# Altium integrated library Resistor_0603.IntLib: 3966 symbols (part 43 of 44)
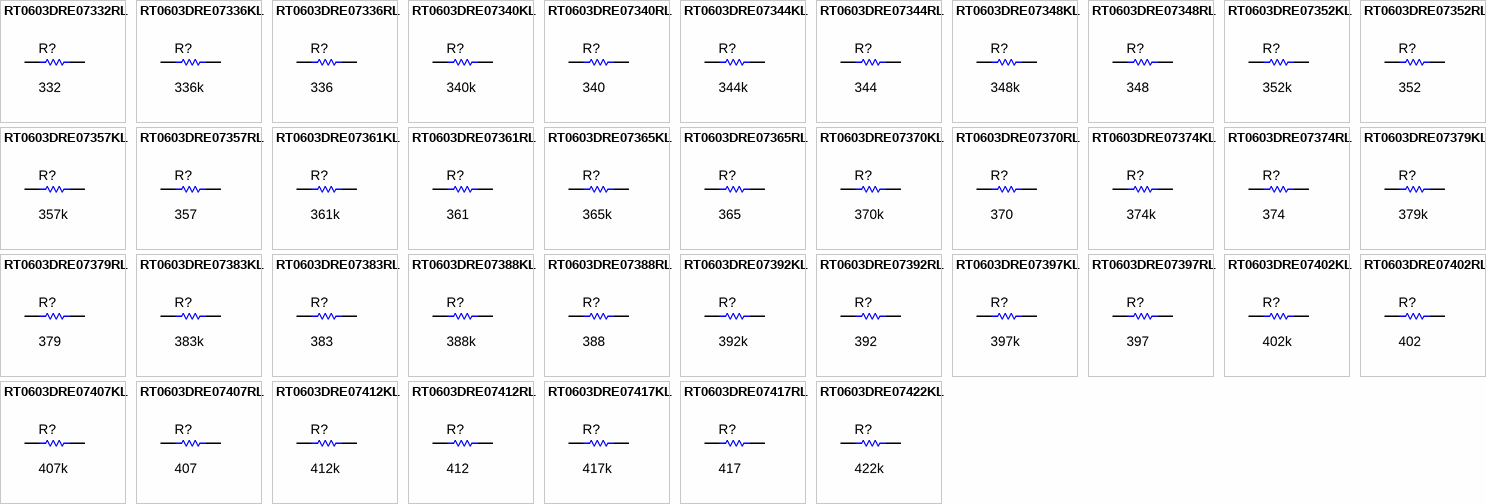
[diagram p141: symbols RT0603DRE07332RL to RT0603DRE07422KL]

## RT0603DRE07422KL
designator R?  ValueDisplayed: 422k  (hidden comment: RT0603DRE07422KL)
RES, 422 k, 0.5%, 0.1 W, 0603; Manufacturer: Yageo America; CompType: Resistor; Value: 422k; Res_ohm: 422000; Tolerance_%: 0.5; Power_W: 0.1; Value2: 0.1W; VDC_V: 75; TempCo: 50 ppm/C; SizeArea_mm2: 1.28; SizeX_mm: 1.6; SizeY_mm: 0.8; SizeZ_mm: 1; EIA_Code: E192; U/M: EA; AEC Category: Q200
signal-integrity model Resistor
simulation model Resistor
footprint 0603
footprint 0603M
footprint 0603L
footprint 0603_HV
footprint 0603S
pins: 1, 2

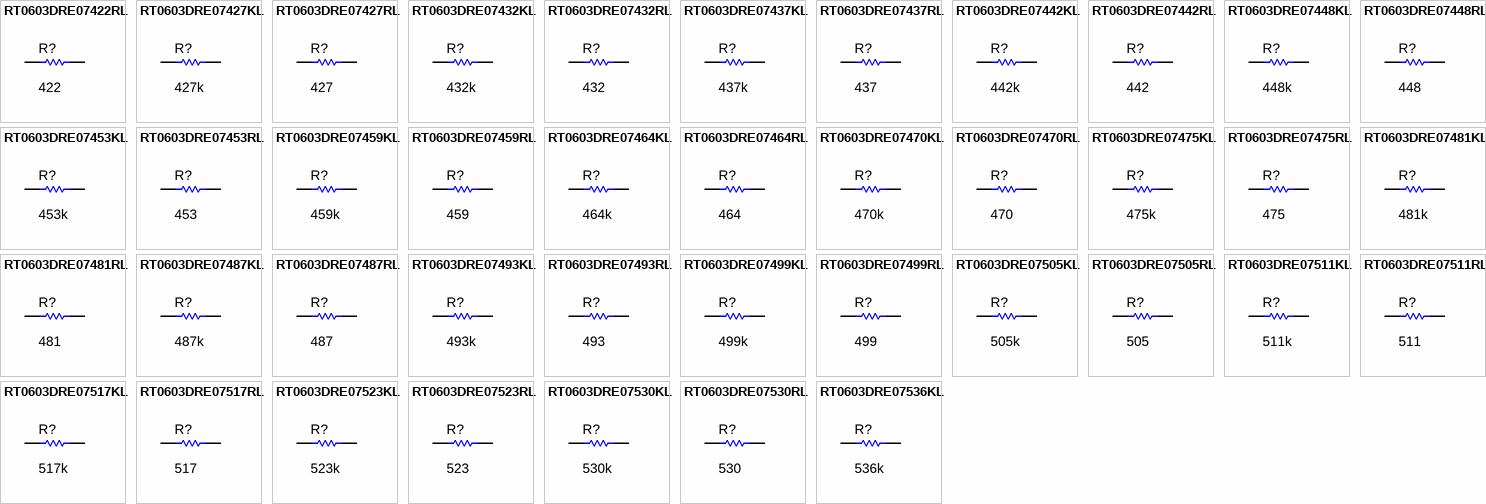
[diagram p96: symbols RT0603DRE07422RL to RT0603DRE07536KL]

## RT0603DRE07422RL
designator R?  ValueDisplayed: 422  (hidden comment: RT0603DRE07422RL)
RES, 422, 0.5%, 0.1 W, 0603; Manufacturer: Yageo America; CompType: Resistor; Value: 422; Value_Code: 422R; Tolerance_%: 0.5; Power_W: 0.1; Value2: 0.1W; VDC_V: 75; TempCo: 50 ppm/C; SizeArea_mm2: 1.28; SizeX_mm: 1.6; SizeY_mm: 0.8; SizeZ_mm: 1; EIA_Code: E192; U/M: EA; AEC Category: Q200
signal-integrity model Resistor
simulation model Resistor
footprint 0603
footprint 0603M
footprint 0603L
footprint 0603_HV
footprint 0603S
pins: 1, 2

## RT0603DRE07427KL
designator R?  ValueDisplayed: 427k  (hidden comment: RT0603DRE07427KL)
RES, 427 k, 0.5%, 0.1 W, 0603; Manufacturer: Yageo America; CompType: Resistor; Value: 427k; Res_ohm: 427000; Tolerance_%: 0.5; Power_W: 0.1; Value2: 0.1W; VDC_V: 75; TempCo: 50 ppm/C; SizeArea_mm2: 1.28; SizeX_mm: 1.6; SizeY_mm: 0.8; SizeZ_mm: 1; EIA_Code: E192; U/M: EA; AEC Category: Q200
signal-integrity model Resistor
simulation model Resistor
footprint 0603
footprint 0603M
footprint 0603L
footprint 0603_HV
footprint 0603S
pins: 1, 2

## RT0603DRE07427RL
designator R?  ValueDisplayed: 427  (hidden comment: RT0603DRE07427RL)
RES, 427, 0.5%, 0.1 W, 0603; Manufacturer: Yageo America; CompType: Resistor; Value: 427; Value_Code: 427R; Tolerance_%: 0.5; Power_W: 0.1; Value2: 0.1W; VDC_V: 75; TempCo: 50 ppm/C; SizeArea_mm2: 1.28; SizeX_mm: 1.6; SizeY_mm: 0.8; SizeZ_mm: 1; EIA_Code: E192; U/M: EA; AEC Category: Q200
signal-integrity model Resistor
simulation model Resistor
footprint 0603
footprint 0603M
footprint 0603L
footprint 0603_HV
footprint 0603S
pins: 1, 2

## RT0603DRE07432KL
designator R?  ValueDisplayed: 432k  (hidden comment: RT0603DRE07432KL)
RES, 432 k, 0.5%, 0.1 W, 0603; Manufacturer: Yageo America; CompType: Resistor; Value: 432k; Res_ohm: 432000; Tolerance_%: 0.5; Power_W: 0.1; Value2: 0.1W; VDC_V: 75; TempCo: 50 ppm/C; SizeArea_mm2: 1.28; SizeX_mm: 1.6; SizeY_mm: 0.8; SizeZ_mm: 1; EIA_Code: E192; U/M: EA; AEC Category: Q200
signal-integrity model Resistor
simulation model Resistor
footprint 0603
footprint 0603M
footprint 0603L
footprint 0603_HV
footprint 0603S
pins: 1, 2

## RT0603DRE07432RL
designator R?  ValueDisplayed: 432  (hidden comment: RT0603DRE07432RL)
RES, 432, 0.5%, 0.1 W, 0603; Manufacturer: Yageo America; CompType: Resistor; Value: 432; Value_Code: 432R; Tolerance_%: 0.5; Power_W: 0.1; Value2: 0.1W; VDC_V: 75; TempCo: 50 ppm/C; SizeArea_mm2: 1.28; SizeX_mm: 1.6; SizeY_mm: 0.8; SizeZ_mm: 1; EIA_Code: E192; U/M: EA; AEC Category: Q200
signal-integrity model Resistor
simulation model Resistor
footprint 0603
footprint 0603M
footprint 0603L
footprint 0603_HV
footprint 0603S
pins: 1, 2

## RT0603DRE07437KL
designator R?  ValueDisplayed: 437k  (hidden comment: RT0603DRE07437KL)
RES, 437 k, 0.5%, 0.1 W, 0603; Manufacturer: Yageo America; CompType: Resistor; Value: 437k; Res_ohm: 437000; Tolerance_%: 0.5; Power_W: 0.1; Value2: 0.1W; VDC_V: 75; TempCo: 50 ppm/C; SizeArea_mm2: 1.28; SizeX_mm: 1.6; SizeY_mm: 0.8; SizeZ_mm: 1; EIA_Code: E192; U/M: EA; AEC Category: Q200
signal-integrity model Resistor
simulation model Resistor
footprint 0603
footprint 0603M
footprint 0603L
footprint 0603_HV
footprint 0603S
pins: 1, 2

## RT0603DRE07437RL
designator R?  ValueDisplayed: 437  (hidden comment: RT0603DRE07437RL)
RES, 437, 0.5%, 0.1 W, 0603; Manufacturer: Yageo America; CompType: Resistor; Value: 437; Value_Code: 437R; Tolerance_%: 0.5; Power_W: 0.1; Value2: 0.1W; VDC_V: 75; TempCo: 50 ppm/C; SizeArea_mm2: 1.28; SizeX_mm: 1.6; SizeY_mm: 0.8; SizeZ_mm: 1; EIA_Code: E192; U/M: EA; AEC Category: Q200
signal-integrity model Resistor
simulation model Resistor
footprint 0603
footprint 0603M
footprint 0603L
footprint 0603_HV
footprint 0603S
pins: 1, 2

## RT0603DRE07442KL
designator R?  ValueDisplayed: 442k  (hidden comment: RT0603DRE07442KL)
RES, 442 k, 0.5%, 0.1 W, 0603; Manufacturer: Yageo America; CompType: Resistor; Value: 442k; Res_ohm: 442000; Tolerance_%: 0.5; Power_W: 0.1; Value2: 0.1W; VDC_V: 75; TempCo: 50 ppm/C; SizeArea_mm2: 1.28; SizeX_mm: 1.6; SizeY_mm: 0.8; SizeZ_mm: 1; EIA_Code: E192; U/M: EA; AEC Category: Q200
signal-integrity model Resistor
simulation model Resistor
footprint 0603
footprint 0603M
footprint 0603L
footprint 0603_HV
footprint 0603S
pins: 1, 2

## RT0603DRE07442RL
designator R?  ValueDisplayed: 442  (hidden comment: RT0603DRE07442RL)
RES, 442, 0.5%, 0.1 W, 0603; Manufacturer: Yageo America; CompType: Resistor; Value: 442; Value_Code: 442R; Tolerance_%: 0.5; Power_W: 0.1; Value2: 0.1W; VDC_V: 75; TempCo: 50 ppm/C; SizeArea_mm2: 1.28; SizeX_mm: 1.6; SizeY_mm: 0.8; SizeZ_mm: 1; EIA_Code: E192; U/M: EA; AEC Category: Q200
signal-integrity model Resistor
simulation model Resistor
footprint 0603
footprint 0603M
footprint 0603L
footprint 0603_HV
footprint 0603S
pins: 1, 2

## RT0603DRE07448KL
designator R?  ValueDisplayed: 448k  (hidden comment: RT0603DRE07448KL)
RES, 448 k, 0.5%, 0.1 W, 0603; Manufacturer: Yageo America; CompType: Resistor; Value: 448k; Res_ohm: 448000; Tolerance_%: 0.5; Power_W: 0.1; Value2: 0.1W; VDC_V: 75; TempCo: 50 ppm/C; SizeArea_mm2: 1.28; SizeX_mm: 1.6; SizeY_mm: 0.8; SizeZ_mm: 1; EIA_Code: E192; U/M: EA; AEC Category: Q200
signal-integrity model Resistor
simulation model Resistor
footprint 0603
footprint 0603M
footprint 0603L
footprint 0603_HV
footprint 0603S
pins: 1, 2

## RT0603DRE07448RL
designator R?  ValueDisplayed: 448  (hidden comment: RT0603DRE07448RL)
RES, 448, 0.5%, 0.1 W, 0603; Manufacturer: Yageo America; CompType: Resistor; Value: 448; Value_Code: 448R; Tolerance_%: 0.5; Power_W: 0.1; Value2: 0.1W; VDC_V: 75; TempCo: 50 ppm/C; SizeArea_mm2: 1.28; SizeX_mm: 1.6; SizeY_mm: 0.8; SizeZ_mm: 1; EIA_Code: E192; U/M: EA; AEC Category: Q200
signal-integrity model Resistor
simulation model Resistor
footprint 0603
footprint 0603M
footprint 0603L
footprint 0603_HV
footprint 0603S
pins: 1, 2

## RT0603DRE07453KL
designator R?  ValueDisplayed: 453k  (hidden comment: RT0603DRE07453KL)
RES, 453 k, 0.5%, 0.1 W, 0603; Manufacturer: Yageo America; CompType: Resistor; Value: 453k; Res_ohm: 453000; Tolerance_%: 0.5; Power_W: 0.1; Value2: 0.1W; VDC_V: 75; TempCo: 50 ppm/C; SizeArea_mm2: 1.28; SizeX_mm: 1.6; SizeY_mm: 0.8; SizeZ_mm: 1; EIA_Code: E192; U/M: EA; AEC Category: Q200
signal-integrity model Resistor
simulation model Resistor
footprint 0603
footprint 0603M
footprint 0603L
footprint 0603_HV
footprint 0603S
pins: 1, 2

## RT0603DRE07453RL
designator R?  ValueDisplayed: 453  (hidden comment: RT0603DRE07453RL)
RES, 453, 0.5%, 0.1 W, 0603; Manufacturer: Yageo America; CompType: Resistor; Value: 453; Value_Code: 453R; Tolerance_%: 0.5; Power_W: 0.1; Value2: 0.1W; VDC_V: 75; TempCo: 50 ppm/C; SizeArea_mm2: 1.28; SizeX_mm: 1.6; SizeY_mm: 0.8; SizeZ_mm: 1; EIA_Code: E192; U/M: EA; AEC Category: Q200
signal-integrity model Resistor
simulation model Resistor
footprint 0603
footprint 0603M
footprint 0603L
footprint 0603_HV
footprint 0603S
pins: 1, 2

## RT0603DRE07459KL
designator R?  ValueDisplayed: 459k  (hidden comment: RT0603DRE07459KL)
RES, 459 k, 0.5%, 0.1 W, 0603; Manufacturer: Yageo America; CompType: Resistor; Value: 459k; Res_ohm: 459000; Tolerance_%: 0.5; Power_W: 0.1; Value2: 0.1W; VDC_V: 75; TempCo: 50 ppm/C; SizeArea_mm2: 1.28; SizeX_mm: 1.6; SizeY_mm: 0.8; SizeZ_mm: 1; EIA_Code: E192; U/M: EA; AEC Category: Q200
signal-integrity model Resistor
simulation model Resistor
footprint 0603
footprint 0603M
footprint 0603L
footprint 0603_HV
footprint 0603S
pins: 1, 2

## RT0603DRE07459RL
designator R?  ValueDisplayed: 459  (hidden comment: RT0603DRE07459RL)
RES, 459, 0.5%, 0.1 W, 0603; Manufacturer: Yageo America; CompType: Resistor; Value: 459; Value_Code: 459R; Tolerance_%: 0.5; Power_W: 0.1; Value2: 0.1W; VDC_V: 75; TempCo: 50 ppm/C; SizeArea_mm2: 1.28; SizeX_mm: 1.6; SizeY_mm: 0.8; SizeZ_mm: 1; EIA_Code: E192; U/M: EA; AEC Category: Q200
signal-integrity model Resistor
simulation model Resistor
footprint 0603
footprint 0603M
footprint 0603L
footprint 0603_HV
footprint 0603S
pins: 1, 2

## RT0603DRE07464KL
designator R?  ValueDisplayed: 464k  (hidden comment: RT0603DRE07464KL)
RES, 464 k, 0.5%, 0.1 W, 0603; Manufacturer: Yageo America; CompType: Resistor; Value: 464k; Res_ohm: 464000; Tolerance_%: 0.5; Power_W: 0.1; Value2: 0.1W; VDC_V: 75; TempCo: 50 ppm/C; SizeArea_mm2: 1.28; SizeX_mm: 1.6; SizeY_mm: 0.8; SizeZ_mm: 1; EIA_Code: E192; U/M: EA; AEC Category: Q200
signal-integrity model Resistor
simulation model Resistor
footprint 0603
footprint 0603M
footprint 0603L
footprint 0603_HV
footprint 0603S
pins: 1, 2

## RT0603DRE07464RL
designator R?  ValueDisplayed: 464  (hidden comment: RT0603DRE07464RL)
RES, 464, 0.5%, 0.1 W, 0603; Manufacturer: Yageo America; CompType: Resistor; Value: 464; Value_Code: 464R; Tolerance_%: 0.5; Power_W: 0.1; Value2: 0.1W; VDC_V: 75; TempCo: 50 ppm/C; SizeArea_mm2: 1.28; SizeX_mm: 1.6; SizeY_mm: 0.8; SizeZ_mm: 1; EIA_Code: E192; U/M: EA; AEC Category: Q200
signal-integrity model Resistor
simulation model Resistor
footprint 0603
footprint 0603M
footprint 0603L
footprint 0603_HV
footprint 0603S
pins: 1, 2

## RT0603DRE07470KL
designator R?  ValueDisplayed: 470k  (hidden comment: RT0603DRE07470KL)
RES, 470 k, 0.5%, 0.1 W, 0603; Manufacturer: Yageo America; CompType: Resistor; Value: 470k; Res_ohm: 470000; Tolerance_%: 0.5; Power_W: 0.1; Value2: 0.1W; VDC_V: 75; TempCo: 50 ppm/C; SizeArea_mm2: 1.28; SizeX_mm: 1.6; SizeY_mm: 0.8; SizeZ_mm: 1; EIA_Code: E192; U/M: EA; AEC Category: Q200
signal-integrity model Resistor
simulation model Resistor
footprint 0603
footprint 0603M
footprint 0603L
footprint 0603_HV
footprint 0603S
pins: 1, 2

## RT0603DRE07470RL
designator R?  ValueDisplayed: 470  (hidden comment: RT0603DRE07470RL)
RES, 470, 0.5%, 0.1 W, 0603; Manufacturer: Yageo America; CompType: Resistor; Value: 470; Value_Code: 470R; Tolerance_%: 0.5; Power_W: 0.1; Value2: 0.1W; VDC_V: 75; TempCo: 50 ppm/C; SizeArea_mm2: 1.28; SizeX_mm: 1.6; SizeY_mm: 0.8; SizeZ_mm: 1; EIA_Code: E192; U/M: EA; AEC Category: Q200
signal-integrity model Resistor
simulation model Resistor
footprint 0603
footprint 0603M
footprint 0603L
footprint 0603_HV
footprint 0603S
pins: 1, 2

## RT0603DRE07475KL
designator R?  ValueDisplayed: 475k  (hidden comment: RT0603DRE07475KL)
RES, 475 k, 0.5%, 0.1 W, 0603; Manufacturer: Yageo America; CompType: Resistor; Value: 475k; Res_ohm: 475000; Tolerance_%: 0.5; Power_W: 0.1; Value2: 0.1W; VDC_V: 75; TempCo: 50 ppm/C; SizeArea_mm2: 1.28; SizeX_mm: 1.6; SizeY_mm: 0.8; SizeZ_mm: 1; EIA_Code: E192; U/M: EA; AEC Category: Q200
signal-integrity model Resistor
simulation model Resistor
footprint 0603
footprint 0603M
footprint 0603L
footprint 0603_HV
footprint 0603S
pins: 1, 2

## RT0603DRE07475RL
designator R?  ValueDisplayed: 475  (hidden comment: RT0603DRE07475RL)
RES, 475, 0.5%, 0.1 W, 0603; Manufacturer: Yageo America; CompType: Resistor; Value: 475; Value_Code: 475R; Tolerance_%: 0.5; Power_W: 0.1; Value2: 0.1W; VDC_V: 75; TempCo: 50 ppm/C; SizeArea_mm2: 1.28; SizeX_mm: 1.6; SizeY_mm: 0.8; SizeZ_mm: 1; EIA_Code: E192; U/M: EA; AEC Category: Q200
signal-integrity model Resistor
simulation model Resistor
footprint 0603
footprint 0603M
footprint 0603L
footprint 0603_HV
footprint 0603S
pins: 1, 2

## RT0603DRE07481KL
designator R?  ValueDisplayed: 481k  (hidden comment: RT0603DRE07481KL)
RES, 481 k, 0.5%, 0.1 W, 0603; Manufacturer: Yageo America; CompType: Resistor; Value: 481k; Res_ohm: 481000; Tolerance_%: 0.5; Power_W: 0.1; Value2: 0.1W; VDC_V: 75; TempCo: 50 ppm/C; SizeArea_mm2: 1.28; SizeX_mm: 1.6; SizeY_mm: 0.8; SizeZ_mm: 1; EIA_Code: E192; U/M: EA; AEC Category: Q200
signal-integrity model Resistor
simulation model Resistor
footprint 0603
footprint 0603M
footprint 0603L
footprint 0603_HV
footprint 0603S
pins: 1, 2

## RT0603DRE07481RL
designator R?  ValueDisplayed: 481  (hidden comment: RT0603DRE07481RL)
RES, 481, 0.5%, 0.1 W, 0603; Manufacturer: Yageo America; CompType: Resistor; Value: 481; Value_Code: 481R; Tolerance_%: 0.5; Power_W: 0.1; Value2: 0.1W; VDC_V: 75; TempCo: 50 ppm/C; SizeArea_mm2: 1.28; SizeX_mm: 1.6; SizeY_mm: 0.8; SizeZ_mm: 1; EIA_Code: E192; U/M: EA; AEC Category: Q200
signal-integrity model Resistor
simulation model Resistor
footprint 0603
footprint 0603M
footprint 0603L
footprint 0603_HV
footprint 0603S
pins: 1, 2

## RT0603DRE07487KL
designator R?  ValueDisplayed: 487k  (hidden comment: RT0603DRE07487KL)
RES, 487 k, 0.5%, 0.1 W, 0603; Manufacturer: Yageo America; CompType: Resistor; Value: 487k; Res_ohm: 487000; Tolerance_%: 0.5; Power_W: 0.1; Value2: 0.1W; VDC_V: 75; TempCo: 50 ppm/C; SizeArea_mm2: 1.28; SizeX_mm: 1.6; SizeY_mm: 0.8; SizeZ_mm: 1; EIA_Code: E192; U/M: EA; AEC Category: Q200
signal-integrity model Resistor
simulation model Resistor
footprint 0603
footprint 0603M
footprint 0603L
footprint 0603_HV
footprint 0603S
pins: 1, 2

## RT0603DRE07487RL
designator R?  ValueDisplayed: 487  (hidden comment: RT0603DRE07487RL)
RES, 487, 0.5%, 0.1 W, 0603; Manufacturer: Yageo America; CompType: Resistor; Value: 487; Value_Code: 487R; Tolerance_%: 0.5; Power_W: 0.1; Value2: 0.1W; VDC_V: 75; TempCo: 50 ppm/C; SizeArea_mm2: 1.28; SizeX_mm: 1.6; SizeY_mm: 0.8; SizeZ_mm: 1; EIA_Code: E192; U/M: EA; AEC Category: Q200
signal-integrity model Resistor
simulation model Resistor
footprint 0603
footprint 0603M
footprint 0603L
footprint 0603_HV
footprint 0603S
pins: 1, 2

## RT0603DRE07493KL
designator R?  ValueDisplayed: 493k  (hidden comment: RT0603DRE07493KL)
RES, 493 k, 0.5%, 0.1 W, 0603; Manufacturer: Yageo America; CompType: Resistor; Value: 493k; Res_ohm: 493000; Tolerance_%: 0.5; Power_W: 0.1; Value2: 0.1W; VDC_V: 75; TempCo: 50 ppm/C; SizeArea_mm2: 1.28; SizeX_mm: 1.6; SizeY_mm: 0.8; SizeZ_mm: 1; EIA_Code: E192; U/M: EA; AEC Category: Q200
signal-integrity model Resistor
simulation model Resistor
footprint 0603
footprint 0603M
footprint 0603L
footprint 0603_HV
footprint 0603S
pins: 1, 2

## RT0603DRE07493RL
designator R?  ValueDisplayed: 493  (hidden comment: RT0603DRE07493RL)
RES, 493, 0.5%, 0.1 W, 0603; Manufacturer: Yageo America; CompType: Resistor; Value: 493; Value_Code: 493R; Tolerance_%: 0.5; Power_W: 0.1; Value2: 0.1W; VDC_V: 75; TempCo: 50 ppm/C; SizeArea_mm2: 1.28; SizeX_mm: 1.6; SizeY_mm: 0.8; SizeZ_mm: 1; EIA_Code: E192; U/M: EA; AEC Category: Q200
signal-integrity model Resistor
simulation model Resistor
footprint 0603
footprint 0603M
footprint 0603L
footprint 0603_HV
footprint 0603S
pins: 1, 2

## RT0603DRE07499KL
designator R?  ValueDisplayed: 499k  (hidden comment: RT0603DRE07499KL)
RES, 499 k, 0.5%, 0.1 W, 0603; Manufacturer: Yageo America; CompType: Resistor; Value: 499k; Res_ohm: 499000; Tolerance_%: 0.5; Power_W: 0.1; Value2: 0.1W; VDC_V: 75; TempCo: 50 ppm/C; SizeArea_mm2: 1.28; SizeX_mm: 1.6; SizeY_mm: 0.8; SizeZ_mm: 1; EIA_Code: E192; U/M: EA; AEC Category: Q200
signal-integrity model Resistor
simulation model Resistor
footprint 0603
footprint 0603M
footprint 0603L
footprint 0603_HV
footprint 0603S
pins: 1, 2

## RT0603DRE07499RL
designator R?  ValueDisplayed: 499  (hidden comment: RT0603DRE07499RL)
RES, 499, 0.5%, 0.1 W, 0603; Manufacturer: Yageo America; CompType: Resistor; Value: 499; Value_Code: 499R; Tolerance_%: 0.5; Power_W: 0.1; Value2: 0.1W; VDC_V: 75; TempCo: 50 ppm/C; SizeArea_mm2: 1.28; SizeX_mm: 1.6; SizeY_mm: 0.8; SizeZ_mm: 1; EIA_Code: E192; U/M: EA; AEC Category: Q200
signal-integrity model Resistor
simulation model Resistor
footprint 0603
footprint 0603M
footprint 0603L
footprint 0603_HV
footprint 0603S
pins: 1, 2

## RT0603DRE07505KL
designator R?  ValueDisplayed: 505k  (hidden comment: RT0603DRE07505KL)
RES, 505 k, 0.5%, 0.1 W, 0603; Manufacturer: Yageo America; CompType: Resistor; Value: 505k; Res_ohm: 505000; Tolerance_%: 0.5; Power_W: 0.1; Value2: 0.1W; VDC_V: 75; TempCo: 50 ppm/C; SizeArea_mm2: 1.28; SizeX_mm: 1.6; SizeY_mm: 0.8; SizeZ_mm: 1; EIA_Code: E192; U/M: EA; AEC Category: Q200
signal-integrity model Resistor
simulation model Resistor
footprint 0603
footprint 0603M
footprint 0603L
footprint 0603_HV
footprint 0603S
pins: 1, 2

## RT0603DRE07505RL
designator R?  ValueDisplayed: 505  (hidden comment: RT0603DRE07505RL)
RES, 505, 0.5%, 0.1 W, 0603; Manufacturer: Yageo America; CompType: Resistor; Value: 505; Value_Code: 505R; Tolerance_%: 0.5; Power_W: 0.1; Value2: 0.1W; VDC_V: 75; TempCo: 50 ppm/C; SizeArea_mm2: 1.28; SizeX_mm: 1.6; SizeY_mm: 0.8; SizeZ_mm: 1; EIA_Code: E192; U/M: EA; AEC Category: Q200
signal-integrity model Resistor
simulation model Resistor
footprint 0603
footprint 0603M
footprint 0603L
footprint 0603_HV
footprint 0603S
pins: 1, 2

## RT0603DRE07511KL
designator R?  ValueDisplayed: 511k  (hidden comment: RT0603DRE07511KL)
RES, 511 k, 0.5%, 0.1 W, 0603; Manufacturer: Yageo America; CompType: Resistor; Value: 511k; Res_ohm: 511000; Tolerance_%: 0.5; Power_W: 0.1; Value2: 0.1W; VDC_V: 75; TempCo: 50 ppm/C; SizeArea_mm2: 1.28; SizeX_mm: 1.6; SizeY_mm: 0.8; SizeZ_mm: 1; EIA_Code: E192; U/M: EA; AEC Category: Q200
signal-integrity model Resistor
simulation model Resistor
footprint 0603
footprint 0603M
footprint 0603L
footprint 0603_HV
footprint 0603S
pins: 1, 2

## RT0603DRE07511RL
designator R?  ValueDisplayed: 511  (hidden comment: RT0603DRE07511RL)
RES, 511, 0.5%, 0.1 W, 0603; Manufacturer: Yageo America; CompType: Resistor; Value: 511; Value_Code: 511R; Tolerance_%: 0.5; Power_W: 0.1; Value2: 0.1W; VDC_V: 75; TempCo: 50 ppm/C; SizeArea_mm2: 1.28; SizeX_mm: 1.6; SizeY_mm: 0.8; SizeZ_mm: 1; EIA_Code: E192; U/M: EA; AEC Category: Q200
signal-integrity model Resistor
simulation model Resistor
footprint 0603
footprint 0603M
footprint 0603L
footprint 0603_HV
footprint 0603S
pins: 1, 2

## RT0603DRE07517KL
designator R?  ValueDisplayed: 517k  (hidden comment: RT0603DRE07517KL)
RES, 517 k, 0.5%, 0.1 W, 0603; Manufacturer: Yageo America; CompType: Resistor; Value: 517k; Res_ohm: 517000; Tolerance_%: 0.5; Power_W: 0.1; Value2: 0.1W; VDC_V: 75; TempCo: 50 ppm/C; SizeArea_mm2: 1.28; SizeX_mm: 1.6; SizeY_mm: 0.8; SizeZ_mm: 1; EIA_Code: E192; U/M: EA; AEC Category: Q200
signal-integrity model Resistor
simulation model Resistor
footprint 0603
footprint 0603M
footprint 0603L
footprint 0603_HV
footprint 0603S
pins: 1, 2

## RT0603DRE07517RL
designator R?  ValueDisplayed: 517  (hidden comment: RT0603DRE07517RL)
RES, 517, 0.5%, 0.1 W, 0603; Manufacturer: Yageo America; CompType: Resistor; Value: 517; Value_Code: 517R; Tolerance_%: 0.5; Power_W: 0.1; Value2: 0.1W; VDC_V: 75; TempCo: 50 ppm/C; SizeArea_mm2: 1.28; SizeX_mm: 1.6; SizeY_mm: 0.8; SizeZ_mm: 1; EIA_Code: E192; U/M: EA; AEC Category: Q200
signal-integrity model Resistor
simulation model Resistor
footprint 0603
footprint 0603M
footprint 0603L
footprint 0603_HV
footprint 0603S
pins: 1, 2

## RT0603DRE07523KL
designator R?  ValueDisplayed: 523k  (hidden comment: RT0603DRE07523KL)
RES, 523 k, 0.5%, 0.1 W, 0603; Manufacturer: Yageo America; CompType: Resistor; Value: 523k; Res_ohm: 523000; Tolerance_%: 0.5; Power_W: 0.1; Value2: 0.1W; VDC_V: 75; TempCo: 50 ppm/C; SizeArea_mm2: 1.28; SizeX_mm: 1.6; SizeY_mm: 0.8; SizeZ_mm: 1; EIA_Code: E192; U/M: EA; AEC Category: Q200
signal-integrity model Resistor
simulation model Resistor
footprint 0603
footprint 0603M
footprint 0603L
footprint 0603_HV
footprint 0603S
pins: 1, 2

## RT0603DRE07523RL
designator R?  ValueDisplayed: 523  (hidden comment: RT0603DRE07523RL)
RES, 523, 0.5%, 0.1 W, 0603; Manufacturer: Yageo America; CompType: Resistor; Value: 523; Value_Code: 523R; Tolerance_%: 0.5; Power_W: 0.1; Value2: 0.1W; VDC_V: 75; TempCo: 50 ppm/C; SizeArea_mm2: 1.28; SizeX_mm: 1.6; SizeY_mm: 0.8; SizeZ_mm: 1; EIA_Code: E192; U/M: EA; AEC Category: Q200
signal-integrity model Resistor
simulation model Resistor
footprint 0603
footprint 0603M
footprint 0603L
footprint 0603_HV
footprint 0603S
pins: 1, 2

## RT0603DRE07530KL
designator R?  ValueDisplayed: 530k  (hidden comment: RT0603DRE07530KL)
RES, 530 k, 0.5%, 0.1 W, 0603; Manufacturer: Yageo America; CompType: Resistor; Value: 530k; Res_ohm: 530000; Tolerance_%: 0.5; Power_W: 0.1; Value2: 0.1W; VDC_V: 75; TempCo: 50 ppm/C; SizeArea_mm2: 1.28; SizeX_mm: 1.6; SizeY_mm: 0.8; SizeZ_mm: 1; EIA_Code: E192; U/M: EA; AEC Category: Q200
signal-integrity model Resistor
simulation model Resistor
footprint 0603
footprint 0603M
footprint 0603L
footprint 0603_HV
footprint 0603S
pins: 1, 2

## RT0603DRE07530RL
designator R?  ValueDisplayed: 530  (hidden comment: RT0603DRE07530RL)
RES, 530, 0.5%, 0.1 W, 0603; Manufacturer: Yageo America; CompType: Resistor; Value: 530; Value_Code: 530R; Tolerance_%: 0.5; Power_W: 0.1; Value2: 0.1W; VDC_V: 75; TempCo: 50 ppm/C; SizeArea_mm2: 1.28; SizeX_mm: 1.6; SizeY_mm: 0.8; SizeZ_mm: 1; EIA_Code: E192; U/M: EA; AEC Category: Q200
signal-integrity model Resistor
simulation model Resistor
footprint 0603
footprint 0603M
footprint 0603L
footprint 0603_HV
footprint 0603S
pins: 1, 2

## RT0603DRE07536KL
designator R?  ValueDisplayed: 536k  (hidden comment: RT0603DRE07536KL)
RES, 536 k, 0.5%, 0.1 W, 0603; Manufacturer: Yageo America; CompType: Resistor; Value: 536k; Res_ohm: 536000; Tolerance_%: 0.5; Power_W: 0.1; Value2: 0.1W; VDC_V: 75; TempCo: 50 ppm/C; SizeArea_mm2: 1.28; SizeX_mm: 1.6; SizeY_mm: 0.8; SizeZ_mm: 1; EIA_Code: E192; U/M: EA; AEC Category: Q200
signal-integrity model Resistor
simulation model Resistor
footprint 0603
footprint 0603M
footprint 0603L
footprint 0603_HV
footprint 0603S
pins: 1, 2

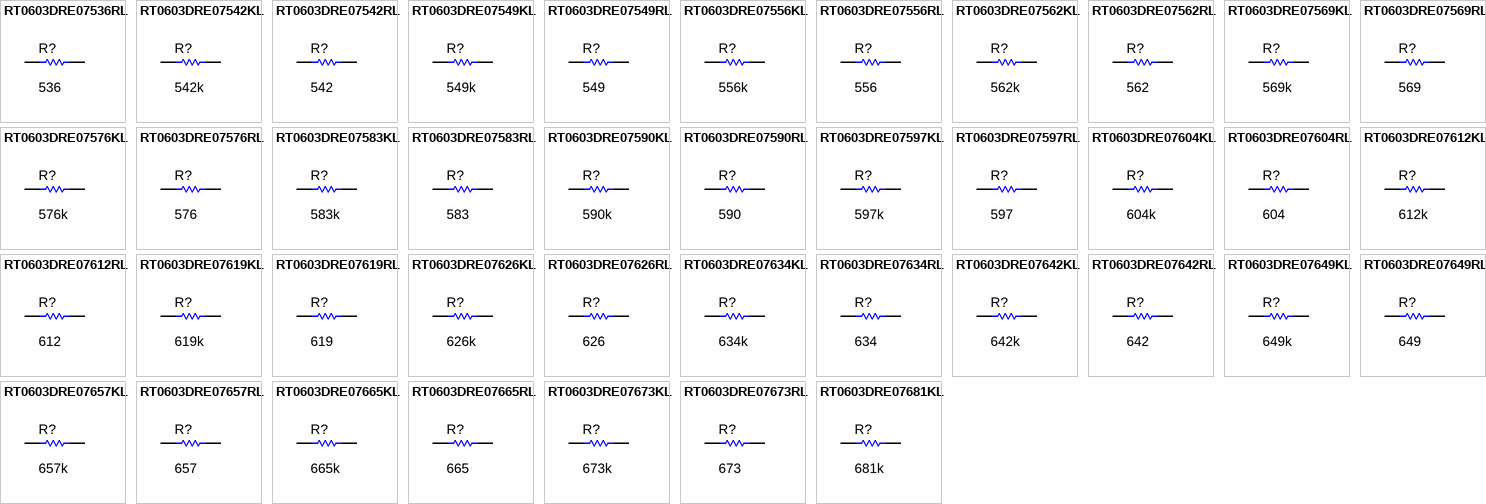
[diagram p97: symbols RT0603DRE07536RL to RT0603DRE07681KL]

## RT0603DRE07536RL
designator R?  ValueDisplayed: 536  (hidden comment: RT0603DRE07536RL)
RES, 536, 0.5%, 0.1 W, 0603; Manufacturer: Yageo America; CompType: Resistor; Value: 536; Value_Code: 536R; Tolerance_%: 0.5; Power_W: 0.1; Value2: 0.1W; VDC_V: 75; TempCo: 50 ppm/C; SizeArea_mm2: 1.28; SizeX_mm: 1.6; SizeY_mm: 0.8; SizeZ_mm: 1; EIA_Code: E192; U/M: EA; AEC Category: Q200
signal-integrity model Resistor
simulation model Resistor
footprint 0603
footprint 0603M
footprint 0603L
footprint 0603_HV
footprint 0603S
pins: 1, 2

## RT0603DRE07542KL
designator R?  ValueDisplayed: 542k  (hidden comment: RT0603DRE07542KL)
RES, 542 k, 0.5%, 0.1 W, 0603; Manufacturer: Yageo America; CompType: Resistor; Value: 542k; Res_ohm: 542000; Tolerance_%: 0.5; Power_W: 0.1; Value2: 0.1W; VDC_V: 75; TempCo: 50 ppm/C; SizeArea_mm2: 1.28; SizeX_mm: 1.6; SizeY_mm: 0.8; SizeZ_mm: 1; EIA_Code: E192; U/M: EA; AEC Category: Q200
signal-integrity model Resistor
simulation model Resistor
footprint 0603
footprint 0603M
footprint 0603L
footprint 0603_HV
footprint 0603S
pins: 1, 2

## RT0603DRE07542RL
designator R?  ValueDisplayed: 542  (hidden comment: RT0603DRE07542RL)
RES, 542, 0.5%, 0.1 W, 0603; Manufacturer: Yageo America; CompType: Resistor; Value: 542; Value_Code: 542R; Tolerance_%: 0.5; Power_W: 0.1; Value2: 0.1W; VDC_V: 75; TempCo: 50 ppm/C; SizeArea_mm2: 1.28; SizeX_mm: 1.6; SizeY_mm: 0.8; SizeZ_mm: 1; EIA_Code: E192; U/M: EA; AEC Category: Q200
signal-integrity model Resistor
simulation model Resistor
footprint 0603
footprint 0603M
footprint 0603L
footprint 0603_HV
footprint 0603S
pins: 1, 2

## RT0603DRE07549KL
designator R?  ValueDisplayed: 549k  (hidden comment: RT0603DRE07549KL)
RES, 549 k, 0.5%, 0.1 W, 0603; Manufacturer: Yageo America; CompType: Resistor; Value: 549k; Res_ohm: 549000; Tolerance_%: 0.5; Power_W: 0.1; Value2: 0.1W; VDC_V: 75; TempCo: 50 ppm/C; SizeArea_mm2: 1.28; SizeX_mm: 1.6; SizeY_mm: 0.8; SizeZ_mm: 1; EIA_Code: E192; U/M: EA; AEC Category: Q200
signal-integrity model Resistor
simulation model Resistor
footprint 0603
footprint 0603M
footprint 0603L
footprint 0603_HV
footprint 0603S
pins: 1, 2

## RT0603DRE07549RL
designator R?  ValueDisplayed: 549  (hidden comment: RT0603DRE07549RL)
RES, 549, 0.5%, 0.1 W, 0603; Manufacturer: Yageo America; CompType: Resistor; Value: 549; Value_Code: 549R; Tolerance_%: 0.5; Power_W: 0.1; Value2: 0.1W; VDC_V: 75; TempCo: 50 ppm/C; SizeArea_mm2: 1.28; SizeX_mm: 1.6; SizeY_mm: 0.8; SizeZ_mm: 1; EIA_Code: E192; U/M: EA; AEC Category: Q200
signal-integrity model Resistor
simulation model Resistor
footprint 0603
footprint 0603M
footprint 0603L
footprint 0603_HV
footprint 0603S
pins: 1, 2

## RT0603DRE07556KL
designator R?  ValueDisplayed: 556k  (hidden comment: RT0603DRE07556KL)
RES, 556 k, 0.5%, 0.1 W, 0603; Manufacturer: Yageo America; CompType: Resistor; Value: 556k; Res_ohm: 556000; Tolerance_%: 0.5; Power_W: 0.1; Value2: 0.1W; VDC_V: 75; TempCo: 50 ppm/C; SizeArea_mm2: 1.28; SizeX_mm: 1.6; SizeY_mm: 0.8; SizeZ_mm: 1; EIA_Code: E192; U/M: EA; AEC Category: Q200
signal-integrity model Resistor
simulation model Resistor
footprint 0603
footprint 0603M
footprint 0603L
footprint 0603_HV
footprint 0603S
pins: 1, 2

## RT0603DRE07556RL
designator R?  ValueDisplayed: 556  (hidden comment: RT0603DRE07556RL)
RES, 556, 0.5%, 0.1 W, 0603; Manufacturer: Yageo America; CompType: Resistor; Value: 556; Value_Code: 556R; Tolerance_%: 0.5; Power_W: 0.1; Value2: 0.1W; VDC_V: 75; TempCo: 50 ppm/C; SizeArea_mm2: 1.28; SizeX_mm: 1.6; SizeY_mm: 0.8; SizeZ_mm: 1; EIA_Code: E192; U/M: EA; AEC Category: Q200
signal-integrity model Resistor
simulation model Resistor
footprint 0603
footprint 0603M
footprint 0603L
footprint 0603_HV
footprint 0603S
pins: 1, 2

## RT0603DRE07562KL
designator R?  ValueDisplayed: 562k  (hidden comment: RT0603DRE07562KL)
RES, 562 k, 0.5%, 0.1 W, 0603; Manufacturer: Yageo America; CompType: Resistor; Value: 562k; Res_ohm: 562000; Tolerance_%: 0.5; Power_W: 0.1; Value2: 0.1W; VDC_V: 75; TempCo: 50 ppm/C; SizeArea_mm2: 1.28; SizeX_mm: 1.6; SizeY_mm: 0.8; SizeZ_mm: 1; EIA_Code: E192; U/M: EA; AEC Category: Q200
signal-integrity model Resistor
simulation model Resistor
footprint 0603
footprint 0603M
footprint 0603L
footprint 0603_HV
footprint 0603S
pins: 1, 2

## RT0603DRE07562RL
designator R?  ValueDisplayed: 562  (hidden comment: RT0603DRE07562RL)
RES, 562, 0.5%, 0.1 W, 0603; Manufacturer: Yageo America; CompType: Resistor; Value: 562; Value_Code: 562R; Tolerance_%: 0.5; Power_W: 0.1; Value2: 0.1W; VDC_V: 75; TempCo: 50 ppm/C; SizeArea_mm2: 1.28; SizeX_mm: 1.6; SizeY_mm: 0.8; SizeZ_mm: 1; EIA_Code: E192; U/M: EA; AEC Category: Q200
signal-integrity model Resistor
simulation model Resistor
footprint 0603
footprint 0603M
footprint 0603L
footprint 0603_HV
footprint 0603S
pins: 1, 2

## RT0603DRE07569KL
designator R?  ValueDisplayed: 569k  (hidden comment: RT0603DRE07569KL)
RES, 569 k, 0.5%, 0.1 W, 0603; Manufacturer: Yageo America; CompType: Resistor; Value: 569k; Res_ohm: 569000; Tolerance_%: 0.5; Power_W: 0.1; Value2: 0.1W; VDC_V: 75; TempCo: 50 ppm/C; SizeArea_mm2: 1.28; SizeX_mm: 1.6; SizeY_mm: 0.8; SizeZ_mm: 1; EIA_Code: E192; U/M: EA; AEC Category: Q200
signal-integrity model Resistor
simulation model Resistor
footprint 0603
footprint 0603M
footprint 0603L
footprint 0603_HV
footprint 0603S
pins: 1, 2

## RT0603DRE07569RL
designator R?  ValueDisplayed: 569  (hidden comment: RT0603DRE07569RL)
RES, 569, 0.5%, 0.1 W, 0603; Manufacturer: Yageo America; CompType: Resistor; Value: 569; Value_Code: 569R; Tolerance_%: 0.5; Power_W: 0.1; Value2: 0.1W; VDC_V: 75; TempCo: 50 ppm/C; SizeArea_mm2: 1.28; SizeX_mm: 1.6; SizeY_mm: 0.8; SizeZ_mm: 1; EIA_Code: E192; U/M: EA; AEC Category: Q200
signal-integrity model Resistor
simulation model Resistor
footprint 0603
footprint 0603M
footprint 0603L
footprint 0603_HV
footprint 0603S
pins: 1, 2

## RT0603DRE07576KL
designator R?  ValueDisplayed: 576k  (hidden comment: RT0603DRE07576KL)
RES, 576 k, 0.5%, 0.1 W, 0603; Manufacturer: Yageo America; CompType: Resistor; Value: 576k; Res_ohm: 576000; Tolerance_%: 0.5; Power_W: 0.1; Value2: 0.1W; VDC_V: 75; TempCo: 50 ppm/C; SizeArea_mm2: 1.28; SizeX_mm: 1.6; SizeY_mm: 0.8; SizeZ_mm: 1; EIA_Code: E192; U/M: EA; AEC Category: Q200
signal-integrity model Resistor
simulation model Resistor
footprint 0603
footprint 0603M
footprint 0603L
footprint 0603_HV
footprint 0603S
pins: 1, 2

## RT0603DRE07576RL
designator R?  ValueDisplayed: 576  (hidden comment: RT0603DRE07576RL)
RES, 576, 0.5%, 0.1 W, 0603; Manufacturer: Yageo America; CompType: Resistor; Value: 576; Value_Code: 576R; Tolerance_%: 0.5; Power_W: 0.1; Value2: 0.1W; VDC_V: 75; TempCo: 50 ppm/C; SizeArea_mm2: 1.28; SizeX_mm: 1.6; SizeY_mm: 0.8; SizeZ_mm: 1; EIA_Code: E192; U/M: EA; AEC Category: Q200
signal-integrity model Resistor
simulation model Resistor
footprint 0603
footprint 0603M
footprint 0603L
footprint 0603_HV
footprint 0603S
pins: 1, 2

## RT0603DRE07583KL
designator R?  ValueDisplayed: 583k  (hidden comment: RT0603DRE07583KL)
RES, 583 k, 0.5%, 0.1 W, 0603; Manufacturer: Yageo America; CompType: Resistor; Value: 583k; Res_ohm: 583000; Tolerance_%: 0.5; Power_W: 0.1; Value2: 0.1W; VDC_V: 75; TempCo: 50 ppm/C; SizeArea_mm2: 1.28; SizeX_mm: 1.6; SizeY_mm: 0.8; SizeZ_mm: 1; EIA_Code: E192; U/M: EA; AEC Category: Q200
signal-integrity model Resistor
simulation model Resistor
footprint 0603
footprint 0603M
footprint 0603L
footprint 0603_HV
footprint 0603S
pins: 1, 2

## RT0603DRE07583RL
designator R?  ValueDisplayed: 583  (hidden comment: RT0603DRE07583RL)
RES, 583, 0.5%, 0.1 W, 0603; Manufacturer: Yageo America; CompType: Resistor; Value: 583; Value_Code: 583R; Tolerance_%: 0.5; Power_W: 0.1; Value2: 0.1W; VDC_V: 75; TempCo: 50 ppm/C; SizeArea_mm2: 1.28; SizeX_mm: 1.6; SizeY_mm: 0.8; SizeZ_mm: 1; EIA_Code: E192; U/M: EA; AEC Category: Q200
signal-integrity model Resistor
simulation model Resistor
footprint 0603
footprint 0603M
footprint 0603L
footprint 0603_HV
footprint 0603S
pins: 1, 2

## RT0603DRE07590KL
designator R?  ValueDisplayed: 590k  (hidden comment: RT0603DRE07590KL)
RES, 590 k, 0.5%, 0.1 W, 0603; Manufacturer: Yageo America; CompType: Resistor; Value: 590k; Res_ohm: 590000; Tolerance_%: 0.5; Power_W: 0.1; Value2: 0.1W; VDC_V: 75; TempCo: 50 ppm/C; SizeArea_mm2: 1.28; SizeX_mm: 1.6; SizeY_mm: 0.8; SizeZ_mm: 1; EIA_Code: E192; U/M: EA; AEC Category: Q200
signal-integrity model Resistor
simulation model Resistor
footprint 0603
footprint 0603M
footprint 0603L
footprint 0603_HV
footprint 0603S
pins: 1, 2

## RT0603DRE07590RL
designator R?  ValueDisplayed: 590  (hidden comment: RT0603DRE07590RL)
RES, 590, 0.5%, 0.1 W, 0603; Manufacturer: Yageo America; CompType: Resistor; Value: 590; Value_Code: 590R; Tolerance_%: 0.5; Power_W: 0.1; Value2: 0.1W; VDC_V: 75; TempCo: 50 ppm/C; SizeArea_mm2: 1.28; SizeX_mm: 1.6; SizeY_mm: 0.8; SizeZ_mm: 1; EIA_Code: E192; U/M: EA; AEC Category: Q200
signal-integrity model Resistor
simulation model Resistor
footprint 0603
footprint 0603M
footprint 0603L
footprint 0603_HV
footprint 0603S
pins: 1, 2

## RT0603DRE07597KL
designator R?  ValueDisplayed: 597k  (hidden comment: RT0603DRE07597KL)
RES, 597 k, 0.5%, 0.1 W, 0603; Manufacturer: Yageo America; CompType: Resistor; Value: 597k; Res_ohm: 597000; Tolerance_%: 0.5; Power_W: 0.1; Value2: 0.1W; VDC_V: 75; TempCo: 50 ppm/C; SizeArea_mm2: 1.28; SizeX_mm: 1.6; SizeY_mm: 0.8; SizeZ_mm: 1; EIA_Code: E192; U/M: EA; AEC Category: Q200
signal-integrity model Resistor
simulation model Resistor
footprint 0603
footprint 0603M
footprint 0603L
footprint 0603_HV
footprint 0603S
pins: 1, 2

## RT0603DRE07597RL
designator R?  ValueDisplayed: 597  (hidden comment: RT0603DRE07597RL)
RES, 597, 0.5%, 0.1 W, 0603; Manufacturer: Yageo America; CompType: Resistor; Value: 597; Value_Code: 597R; Tolerance_%: 0.5; Power_W: 0.1; Value2: 0.1W; VDC_V: 75; TempCo: 50 ppm/C; SizeArea_mm2: 1.28; SizeX_mm: 1.6; SizeY_mm: 0.8; SizeZ_mm: 1; EIA_Code: E192; U/M: EA; AEC Category: Q200
signal-integrity model Resistor
simulation model Resistor
footprint 0603
footprint 0603M
footprint 0603L
footprint 0603_HV
footprint 0603S
pins: 1, 2

## RT0603DRE07604KL
designator R?  ValueDisplayed: 604k  (hidden comment: RT0603DRE07604KL)
RES, 604 k, 0.5%, 0.1 W, 0603; Manufacturer: Yageo America; CompType: Resistor; Value: 604k; Res_ohm: 604000; Tolerance_%: 0.5; Power_W: 0.1; Value2: 0.1W; VDC_V: 75; TempCo: 50 ppm/C; SizeArea_mm2: 1.28; SizeX_mm: 1.6; SizeY_mm: 0.8; SizeZ_mm: 1; EIA_Code: E192; U/M: EA; AEC Category: Q200
signal-integrity model Resistor
simulation model Resistor
footprint 0603
footprint 0603M
footprint 0603L
footprint 0603_HV
footprint 0603S
pins: 1, 2

## RT0603DRE07604RL
designator R?  ValueDisplayed: 604  (hidden comment: RT0603DRE07604RL)
RES, 604, 0.5%, 0.1 W, 0603; Manufacturer: Yageo America; CompType: Resistor; Value: 604; Value_Code: 604R; Tolerance_%: 0.5; Power_W: 0.1; Value2: 0.1W; VDC_V: 75; TempCo: 50 ppm/C; SizeArea_mm2: 1.28; SizeX_mm: 1.6; SizeY_mm: 0.8; SizeZ_mm: 1; EIA_Code: E192; U/M: EA; AEC Category: Q200
signal-integrity model Resistor
simulation model Resistor
footprint 0603
footprint 0603M
footprint 0603L
footprint 0603_HV
footprint 0603S
pins: 1, 2

## RT0603DRE07612KL
designator R?  ValueDisplayed: 612k  (hidden comment: RT0603DRE07612KL)
RES, 612 k, 0.5%, 0.1 W, 0603; Manufacturer: Yageo America; CompType: Resistor; Value: 612k; Res_ohm: 612000; Tolerance_%: 0.5; Power_W: 0.1; Value2: 0.1W; VDC_V: 75; TempCo: 50 ppm/C; SizeArea_mm2: 1.28; SizeX_mm: 1.6; SizeY_mm: 0.8; SizeZ_mm: 1; EIA_Code: E192; U/M: EA; AEC Category: Q200
signal-integrity model Resistor
simulation model Resistor
footprint 0603
footprint 0603M
footprint 0603L
footprint 0603_HV
footprint 0603S
pins: 1, 2

## RT0603DRE07612RL
designator R?  ValueDisplayed: 612  (hidden comment: RT0603DRE07612RL)
RES, 612, 0.5%, 0.1 W, 0603; Manufacturer: Yageo America; CompType: Resistor; Value: 612; Value_Code: 612R; Tolerance_%: 0.5; Power_W: 0.1; Value2: 0.1W; VDC_V: 75; TempCo: 50 ppm/C; SizeArea_mm2: 1.28; SizeX_mm: 1.6; SizeY_mm: 0.8; SizeZ_mm: 1; EIA_Code: E192; U/M: EA; AEC Category: Q200
signal-integrity model Resistor
simulation model Resistor
footprint 0603
footprint 0603M
footprint 0603L
footprint 0603_HV
footprint 0603S
pins: 1, 2

## RT0603DRE07619KL
designator R?  ValueDisplayed: 619k  (hidden comment: RT0603DRE07619KL)
RES, 619 k, 0.5%, 0.1 W, 0603; Manufacturer: Yageo America; CompType: Resistor; Value: 619k; Res_ohm: 619000; Tolerance_%: 0.5; Power_W: 0.1; Value2: 0.1W; VDC_V: 75; TempCo: 50 ppm/C; SizeArea_mm2: 1.28; SizeX_mm: 1.6; SizeY_mm: 0.8; SizeZ_mm: 1; EIA_Code: E192; U/M: EA; AEC Category: Q200
signal-integrity model Resistor
simulation model Resistor
footprint 0603
footprint 0603M
footprint 0603L
footprint 0603_HV
footprint 0603S
pins: 1, 2

## RT0603DRE07619RL
designator R?  ValueDisplayed: 619  (hidden comment: RT0603DRE07619RL)
RES, 619, 0.5%, 0.1 W, 0603; Manufacturer: Yageo America; CompType: Resistor; Value: 619; Value_Code: 619R; Tolerance_%: 0.5; Power_W: 0.1; Value2: 0.1W; VDC_V: 75; TempCo: 50 ppm/C; SizeArea_mm2: 1.28; SizeX_mm: 1.6; SizeY_mm: 0.8; SizeZ_mm: 1; EIA_Code: E192; U/M: EA; AEC Category: Q200
signal-integrity model Resistor
simulation model Resistor
footprint 0603
footprint 0603M
footprint 0603L
footprint 0603_HV
footprint 0603S
pins: 1, 2

## RT0603DRE07626KL
designator R?  ValueDisplayed: 626k  (hidden comment: RT0603DRE07626KL)
RES, 626 k, 0.5%, 0.1 W, 0603; Manufacturer: Yageo America; CompType: Resistor; Value: 626k; Res_ohm: 626000; Tolerance_%: 0.5; Power_W: 0.1; Value2: 0.1W; VDC_V: 75; TempCo: 50 ppm/C; SizeArea_mm2: 1.28; SizeX_mm: 1.6; SizeY_mm: 0.8; SizeZ_mm: 1; EIA_Code: E192; U/M: EA; AEC Category: Q200
signal-integrity model Resistor
simulation model Resistor
footprint 0603
footprint 0603M
footprint 0603L
footprint 0603_HV
footprint 0603S
pins: 1, 2

## RT0603DRE07626RL
designator R?  ValueDisplayed: 626  (hidden comment: RT0603DRE07626RL)
RES, 626, 0.5%, 0.1 W, 0603; Manufacturer: Yageo America; CompType: Resistor; Value: 626; Value_Code: 626R; Tolerance_%: 0.5; Power_W: 0.1; Value2: 0.1W; VDC_V: 75; TempCo: 50 ppm/C; SizeArea_mm2: 1.28; SizeX_mm: 1.6; SizeY_mm: 0.8; SizeZ_mm: 1; EIA_Code: E192; U/M: EA; AEC Category: Q200
signal-integrity model Resistor
simulation model Resistor
footprint 0603
footprint 0603M
footprint 0603L
footprint 0603_HV
footprint 0603S
pins: 1, 2

## RT0603DRE07634KL
designator R?  ValueDisplayed: 634k  (hidden comment: RT0603DRE07634KL)
RES, 634 k, 0.5%, 0.1 W, 0603; Manufacturer: Yageo America; CompType: Resistor; Value: 634k; Res_ohm: 634000; Tolerance_%: 0.5; Power_W: 0.1; Value2: 0.1W; VDC_V: 75; TempCo: 50 ppm/C; SizeArea_mm2: 1.28; SizeX_mm: 1.6; SizeY_mm: 0.8; SizeZ_mm: 1; EIA_Code: E192; U/M: EA; AEC Category: Q200
signal-integrity model Resistor
simulation model Resistor
footprint 0603
footprint 0603M
footprint 0603L
footprint 0603_HV
footprint 0603S
pins: 1, 2

## RT0603DRE07634RL
designator R?  ValueDisplayed: 634  (hidden comment: RT0603DRE07634RL)
RES, 634, 0.5%, 0.1 W, 0603; Manufacturer: Yageo America; CompType: Resistor; Value: 634; Value_Code: 634R; Tolerance_%: 0.5; Power_W: 0.1; Value2: 0.1W; VDC_V: 75; TempCo: 50 ppm/C; SizeArea_mm2: 1.28; SizeX_mm: 1.6; SizeY_mm: 0.8; SizeZ_mm: 1; EIA_Code: E192; U/M: EA; AEC Category: Q200
signal-integrity model Resistor
simulation model Resistor
footprint 0603
footprint 0603M
footprint 0603L
footprint 0603_HV
footprint 0603S
pins: 1, 2

## RT0603DRE07642KL
designator R?  ValueDisplayed: 642k  (hidden comment: RT0603DRE07642KL)
RES, 642 k, 0.5%, 0.1 W, 0603; Manufacturer: Yageo America; CompType: Resistor; Value: 642k; Res_ohm: 642000; Tolerance_%: 0.5; Power_W: 0.1; Value2: 0.1W; VDC_V: 75; TempCo: 50 ppm/C; SizeArea_mm2: 1.28; SizeX_mm: 1.6; SizeY_mm: 0.8; SizeZ_mm: 1; EIA_Code: E192; U/M: EA; AEC Category: Q200
signal-integrity model Resistor
simulation model Resistor
footprint 0603
footprint 0603M
footprint 0603L
footprint 0603_HV
footprint 0603S
pins: 1, 2

## RT0603DRE07642RL
designator R?  ValueDisplayed: 642  (hidden comment: RT0603DRE07642RL)
RES, 642, 0.5%, 0.1 W, 0603; Manufacturer: Yageo America; CompType: Resistor; Value: 642; Value_Code: 642R; Tolerance_%: 0.5; Power_W: 0.1; Value2: 0.1W; VDC_V: 75; TempCo: 50 ppm/C; SizeArea_mm2: 1.28; SizeX_mm: 1.6; SizeY_mm: 0.8; SizeZ_mm: 1; EIA_Code: E192; U/M: EA; AEC Category: Q200
signal-integrity model Resistor
simulation model Resistor
footprint 0603
footprint 0603M
footprint 0603L
footprint 0603_HV
footprint 0603S
pins: 1, 2

## RT0603DRE07649KL
designator R?  ValueDisplayed: 649k  (hidden comment: RT0603DRE07649KL)
RES, 649 k, 0.5%, 0.1 W, 0603; Manufacturer: Yageo America; CompType: Resistor; Value: 649k; Res_ohm: 649000; Tolerance_%: 0.5; Power_W: 0.1; Value2: 0.1W; VDC_V: 75; TempCo: 50 ppm/C; SizeArea_mm2: 1.28; SizeX_mm: 1.6; SizeY_mm: 0.8; SizeZ_mm: 1; EIA_Code: E192; U/M: EA; AEC Category: Q200
signal-integrity model Resistor
simulation model Resistor
footprint 0603
footprint 0603M
footprint 0603L
footprint 0603_HV
footprint 0603S
pins: 1, 2

## RT0603DRE07649RL
designator R?  ValueDisplayed: 649  (hidden comment: RT0603DRE07649RL)
RES, 649, 0.5%, 0.1 W, 0603; Manufacturer: Yageo America; CompType: Resistor; Value: 649; Value_Code: 649R; Tolerance_%: 0.5; Power_W: 0.1; Value2: 0.1W; VDC_V: 75; TempCo: 50 ppm/C; SizeArea_mm2: 1.28; SizeX_mm: 1.6; SizeY_mm: 0.8; SizeZ_mm: 1; EIA_Code: E192; U/M: EA; AEC Category: Q200
signal-integrity model Resistor
simulation model Resistor
footprint 0603
footprint 0603M
footprint 0603L
footprint 0603_HV
footprint 0603S
pins: 1, 2

## RT0603DRE07657KL
designator R?  ValueDisplayed: 657k  (hidden comment: RT0603DRE07657KL)
RES, 657 k, 0.5%, 0.1 W, 0603; Manufacturer: Yageo America; CompType: Resistor; Value: 657k; Res_ohm: 657000; Tolerance_%: 0.5; Power_W: 0.1; Value2: 0.1W; VDC_V: 75; TempCo: 50 ppm/C; SizeArea_mm2: 1.28; SizeX_mm: 1.6; SizeY_mm: 0.8; SizeZ_mm: 1; EIA_Code: E192; U/M: EA; AEC Category: Q200
signal-integrity model Resistor
simulation model Resistor
footprint 0603
footprint 0603M
footprint 0603L
footprint 0603_HV
footprint 0603S
pins: 1, 2

## RT0603DRE07657RL
designator R?  ValueDisplayed: 657  (hidden comment: RT0603DRE07657RL)
RES, 657, 0.5%, 0.1 W, 0603; Manufacturer: Yageo America; CompType: Resistor; Value: 657; Value_Code: 657R; Tolerance_%: 0.5; Power_W: 0.1; Value2: 0.1W; VDC_V: 75; TempCo: 50 ppm/C; SizeArea_mm2: 1.28; SizeX_mm: 1.6; SizeY_mm: 0.8; SizeZ_mm: 1; EIA_Code: E192; U/M: EA; AEC Category: Q200
signal-integrity model Resistor
simulation model Resistor
footprint 0603
footprint 0603M
footprint 0603L
footprint 0603_HV
footprint 0603S
pins: 1, 2

## RT0603DRE07665KL
designator R?  ValueDisplayed: 665k  (hidden comment: RT0603DRE07665KL)
RES, 665 k, 0.5%, 0.1 W, 0603; Manufacturer: Yageo America; CompType: Resistor; Value: 665k; Res_ohm: 665000; Tolerance_%: 0.5; Power_W: 0.1; Value2: 0.1W; VDC_V: 75; TempCo: 50 ppm/C; SizeArea_mm2: 1.28; SizeX_mm: 1.6; SizeY_mm: 0.8; SizeZ_mm: 1; EIA_Code: E192; U/M: EA; AEC Category: Q200
signal-integrity model Resistor
simulation model Resistor
footprint 0603
footprint 0603M
footprint 0603L
footprint 0603_HV
footprint 0603S
pins: 1, 2

## RT0603DRE07665RL
designator R?  ValueDisplayed: 665  (hidden comment: RT0603DRE07665RL)
RES, 665, 0.5%, 0.1 W, 0603; Manufacturer: Yageo America; CompType: Resistor; Value: 665; Value_Code: 665R; Tolerance_%: 0.5; Power_W: 0.1; Value2: 0.1W; VDC_V: 75; TempCo: 50 ppm/C; SizeArea_mm2: 1.28; SizeX_mm: 1.6; SizeY_mm: 0.8; SizeZ_mm: 1; EIA_Code: E192; U/M: EA; AEC Category: Q200
signal-integrity model Resistor
simulation model Resistor
footprint 0603
footprint 0603M
footprint 0603L
footprint 0603_HV
footprint 0603S
pins: 1, 2

## RT0603DRE07673KL
designator R?  ValueDisplayed: 673k  (hidden comment: RT0603DRE07673KL)
RES, 673 k, 0.5%, 0.1 W, 0603; Manufacturer: Yageo America; CompType: Resistor; Value: 673k; Res_ohm: 673000; Tolerance_%: 0.5; Power_W: 0.1; Value2: 0.1W; VDC_V: 75; TempCo: 50 ppm/C; SizeArea_mm2: 1.28; SizeX_mm: 1.6; SizeY_mm: 0.8; SizeZ_mm: 1; EIA_Code: E192; U/M: EA; AEC Category: Q200
signal-integrity model Resistor
simulation model Resistor
footprint 0603
footprint 0603M
footprint 0603L
footprint 0603_HV
footprint 0603S
pins: 1, 2

## RT0603DRE07673RL
designator R?  ValueDisplayed: 673  (hidden comment: RT0603DRE07673RL)
RES, 673, 0.5%, 0.1 W, 0603; Manufacturer: Yageo America; CompType: Resistor; Value: 673; Value_Code: 673R; Tolerance_%: 0.5; Power_W: 0.1; Value2: 0.1W; VDC_V: 75; TempCo: 50 ppm/C; SizeArea_mm2: 1.28; SizeX_mm: 1.6; SizeY_mm: 0.8; SizeZ_mm: 1; EIA_Code: E192; U/M: EA; AEC Category: Q200
signal-integrity model Resistor
simulation model Resistor
footprint 0603
footprint 0603M
footprint 0603L
footprint 0603_HV
footprint 0603S
pins: 1, 2

## RT0603DRE07681KL
designator R?  ValueDisplayed: 681k  (hidden comment: RT0603DRE07681KL)
RES, 681 k, 0.5%, 0.1 W, 0603; Manufacturer: Yageo America; CompType: Resistor; Value: 681k; Res_ohm: 681000; Tolerance_%: 0.5; Power_W: 0.1; Value2: 0.1W; VDC_V: 75; TempCo: 50 ppm/C; SizeArea_mm2: 1.28; SizeX_mm: 1.6; SizeY_mm: 0.8; SizeZ_mm: 1; EIA_Code: E192; U/M: EA; AEC Category: Q200
signal-integrity model Resistor
simulation model Resistor
footprint 0603
footprint 0603M
footprint 0603L
footprint 0603_HV
footprint 0603S
pins: 1, 2

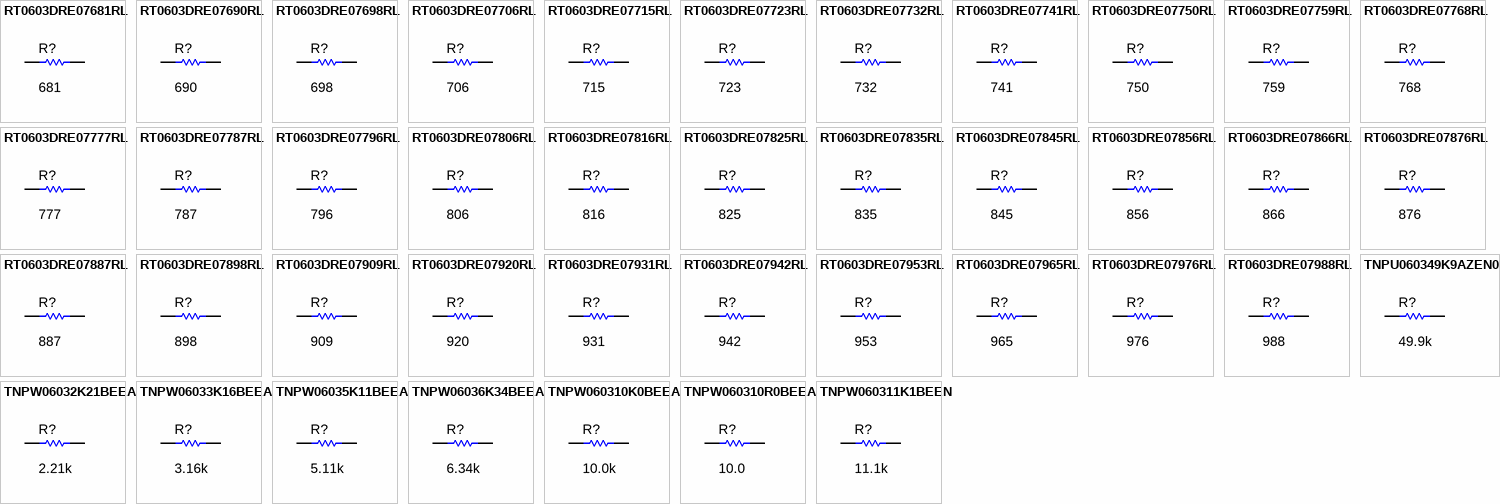
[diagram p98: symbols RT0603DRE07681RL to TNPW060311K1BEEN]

## RT0603DRE07681RL
designator R?  ValueDisplayed: 681  (hidden comment: RT0603DRE07681RL)
RES, 681, 0.5%, 0.1 W, 0603; Manufacturer: Yageo America; CompType: Resistor; Value: 681; Value_Code: 681R; Tolerance_%: 0.5; Power_W: 0.1; Value2: 0.1W; VDC_V: 75; TempCo: 50 ppm/C; SizeArea_mm2: 1.28; SizeX_mm: 1.6; SizeY_mm: 0.8; SizeZ_mm: 1; EIA_Code: E192; U/M: EA; AEC Category: Q200
signal-integrity model Resistor
simulation model Resistor
footprint 0603
footprint 0603M
footprint 0603L
footprint 0603_HV
footprint 0603S
pins: 1, 2

## RT0603DRE07690RL
designator R?  ValueDisplayed: 690  (hidden comment: RT0603DRE07690RL)
RES, 690, 0.5%, 0.1 W, 0603; Manufacturer: Yageo America; CompType: Resistor; Value: 690; Value_Code: 690R; Tolerance_%: 0.5; Power_W: 0.1; Value2: 0.1W; VDC_V: 75; TempCo: 50 ppm/C; SizeArea_mm2: 1.28; SizeX_mm: 1.6; SizeY_mm: 0.8; SizeZ_mm: 1; EIA_Code: E192; U/M: EA; AEC Category: Q200
signal-integrity model Resistor
simulation model Resistor
footprint 0603
footprint 0603M
footprint 0603L
footprint 0603_HV
footprint 0603S
pins: 1, 2

## RT0603DRE07698RL
designator R?  ValueDisplayed: 698  (hidden comment: RT0603DRE07698RL)
RES, 698, 0.5%, 0.1 W, 0603; Manufacturer: Yageo America; CompType: Resistor; Value: 698; Value_Code: 698R; Tolerance_%: 0.5; Power_W: 0.1; Value2: 0.1W; VDC_V: 75; TempCo: 50 ppm/C; SizeArea_mm2: 1.28; SizeX_mm: 1.6; SizeY_mm: 0.8; SizeZ_mm: 1; EIA_Code: E192; U/M: EA; AEC Category: Q200
signal-integrity model Resistor
simulation model Resistor
footprint 0603
footprint 0603M
footprint 0603L
footprint 0603_HV
footprint 0603S
pins: 1, 2

## RT0603DRE07706RL
designator R?  ValueDisplayed: 706  (hidden comment: RT0603DRE07706RL)
RES, 706, 0.5%, 0.1 W, 0603; Manufacturer: Yageo America; CompType: Resistor; Value: 706; Value_Code: 706R; Tolerance_%: 0.5; Power_W: 0.1; Value2: 0.1W; VDC_V: 75; TempCo: 50 ppm/C; SizeArea_mm2: 1.28; SizeX_mm: 1.6; SizeY_mm: 0.8; SizeZ_mm: 1; EIA_Code: E192; U/M: EA; AEC Category: Q200
signal-integrity model Resistor
simulation model Resistor
footprint 0603
footprint 0603M
footprint 0603L
footprint 0603_HV
footprint 0603S
pins: 1, 2

## RT0603DRE07715RL
designator R?  ValueDisplayed: 715  (hidden comment: RT0603DRE07715RL)
RES, 715, 0.5%, 0.1 W, 0603; Manufacturer: Yageo America; CompType: Resistor; Value: 715; Value_Code: 715R; Tolerance_%: 0.5; Power_W: 0.1; Value2: 0.1W; VDC_V: 75; TempCo: 50 ppm/C; SizeArea_mm2: 1.28; SizeX_mm: 1.6; SizeY_mm: 0.8; SizeZ_mm: 1; EIA_Code: E192; U/M: EA; AEC Category: Q200
signal-integrity model Resistor
simulation model Resistor
footprint 0603
footprint 0603M
footprint 0603L
footprint 0603_HV
footprint 0603S
pins: 1, 2

## RT0603DRE07723RL
designator R?  ValueDisplayed: 723  (hidden comment: RT0603DRE07723RL)
RES, 723, 0.5%, 0.1 W, 0603; Manufacturer: Yageo America; CompType: Resistor; Value: 723; Value_Code: 723R; Tolerance_%: 0.5; Power_W: 0.1; Value2: 0.1W; VDC_V: 75; TempCo: 50 ppm/C; SizeArea_mm2: 1.28; SizeX_mm: 1.6; SizeY_mm: 0.8; SizeZ_mm: 1; EIA_Code: E192; U/M: EA; AEC Category: Q200
signal-integrity model Resistor
simulation model Resistor
footprint 0603
footprint 0603M
footprint 0603L
footprint 0603_HV
footprint 0603S
pins: 1, 2

## RT0603DRE07732RL
designator R?  ValueDisplayed: 732  (hidden comment: RT0603DRE07732RL)
RES, 732, 0.5%, 0.1 W, 0603; Manufacturer: Yageo America; CompType: Resistor; Value: 732; Value_Code: 732R; Tolerance_%: 0.5; Power_W: 0.1; Value2: 0.1W; VDC_V: 75; TempCo: 50 ppm/C; SizeArea_mm2: 1.28; SizeX_mm: 1.6; SizeY_mm: 0.8; SizeZ_mm: 1; EIA_Code: E192; U/M: EA; AEC Category: Q200
signal-integrity model Resistor
simulation model Resistor
footprint 0603
footprint 0603M
footprint 0603L
footprint 0603_HV
footprint 0603S
pins: 1, 2

## RT0603DRE07741RL
designator R?  ValueDisplayed: 741  (hidden comment: RT0603DRE07741RL)
RES, 741, 0.5%, 0.1 W, 0603; Manufacturer: Yageo America; CompType: Resistor; Value: 741; Value_Code: 741R; Tolerance_%: 0.5; Power_W: 0.1; Value2: 0.1W; VDC_V: 75; TempCo: 50 ppm/C; SizeArea_mm2: 1.28; SizeX_mm: 1.6; SizeY_mm: 0.8; SizeZ_mm: 1; EIA_Code: E192; U/M: EA; AEC Category: Q200
signal-integrity model Resistor
simulation model Resistor
footprint 0603
footprint 0603M
footprint 0603L
footprint 0603_HV
footprint 0603S
pins: 1, 2

## RT0603DRE07750RL
designator R?  ValueDisplayed: 750  (hidden comment: RT0603DRE07750RL)
RES, 750, 0.5%, 0.1 W, 0603; Manufacturer: Yageo America; CompType: Resistor; Value: 750; Value_Code: 750R; Tolerance_%: 0.5; Power_W: 0.1; Value2: 0.1W; VDC_V: 75; TempCo: 50 ppm/C; SizeArea_mm2: 1.28; SizeX_mm: 1.6; SizeY_mm: 0.8; SizeZ_mm: 1; EIA_Code: E192; U/M: EA; AEC Category: Q200
signal-integrity model Resistor
simulation model Resistor
footprint 0603
footprint 0603M
footprint 0603L
footprint 0603_HV
footprint 0603S
pins: 1, 2

## RT0603DRE07759RL
designator R?  ValueDisplayed: 759  (hidden comment: RT0603DRE07759RL)
RES, 759, 0.5%, 0.1 W, 0603; Manufacturer: Yageo America; CompType: Resistor; Value: 759; Value_Code: 759R; Tolerance_%: 0.5; Power_W: 0.1; Value2: 0.1W; VDC_V: 75; TempCo: 50 ppm/C; SizeArea_mm2: 1.28; SizeX_mm: 1.6; SizeY_mm: 0.8; SizeZ_mm: 1; EIA_Code: E192; U/M: EA; AEC Category: Q200
signal-integrity model Resistor
simulation model Resistor
footprint 0603
footprint 0603M
footprint 0603L
footprint 0603_HV
footprint 0603S
pins: 1, 2

## RT0603DRE07768RL
designator R?  ValueDisplayed: 768  (hidden comment: RT0603DRE07768RL)
RES, 768, 0.5%, 0.1 W, 0603; Manufacturer: Yageo America; CompType: Resistor; Value: 768; Value_Code: 768R; Tolerance_%: 0.5; Power_W: 0.1; Value2: 0.1W; VDC_V: 75; TempCo: 50 ppm/C; SizeArea_mm2: 1.28; SizeX_mm: 1.6; SizeY_mm: 0.8; SizeZ_mm: 1; EIA_Code: E192; U/M: EA; AEC Category: Q200
signal-integrity model Resistor
simulation model Resistor
footprint 0603
footprint 0603M
footprint 0603L
footprint 0603_HV
footprint 0603S
pins: 1, 2

## RT0603DRE07777RL
designator R?  ValueDisplayed: 777  (hidden comment: RT0603DRE07777RL)
RES, 777, 0.5%, 0.1 W, 0603; Manufacturer: Yageo America; CompType: Resistor; Value: 777; Value_Code: 777R; Tolerance_%: 0.5; Power_W: 0.1; Value2: 0.1W; VDC_V: 75; TempCo: 50 ppm/C; SizeArea_mm2: 1.28; SizeX_mm: 1.6; SizeY_mm: 0.8; SizeZ_mm: 1; EIA_Code: E192; U/M: EA; AEC Category: Q200
signal-integrity model Resistor
simulation model Resistor
footprint 0603
footprint 0603M
footprint 0603L
footprint 0603_HV
footprint 0603S
pins: 1, 2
